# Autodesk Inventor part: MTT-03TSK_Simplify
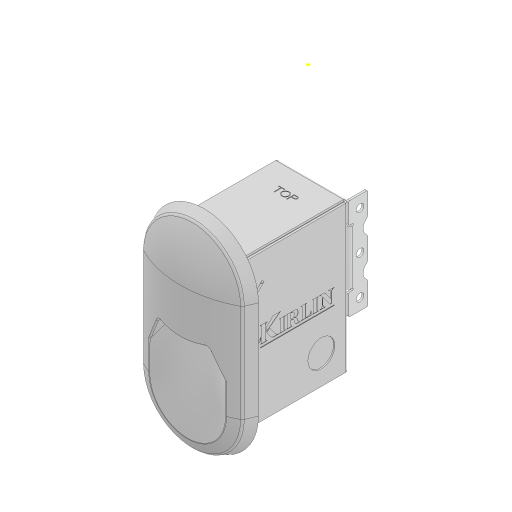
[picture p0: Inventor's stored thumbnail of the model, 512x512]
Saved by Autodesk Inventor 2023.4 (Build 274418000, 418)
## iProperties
Created: 2024-02
Part Number: MTT-03TSK_Simplify
Material: Generic
Document SubType Name: Modeling
Designer: sjaafar
Mass: 133.424 g
Surface Area: 1388.59 cm^2
Volume: 133.424 cm^3
Density: 1 g/cm^3
Appearance: Default
description: 0:0:Hitsville Task Light
manufacturer: 0:0:The Kirlin Company
model: 0:0:MTT-03TSK
url: 0:0:
load_classification: Lighting
motor: 0 ul
Author: sjaafar
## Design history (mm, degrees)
derived "MTT-03TSKR.iam"
  node "902001-00-00.iam:1::902000-00-00.iam:1"
body "Solid1"
node "904003-XX-XX.iam:1::503002-00-00.ipt:1"
node "904003-XX-XX.iam:1::503002-00-00.ipt:2"
node "904003-XX-XX.iam:1::510200-00-00.ipt:1"
node "904003-XX-XX.iam:1::502308-00-00.ipt:1"
node "904003-XX-XX.iam:1::502308-00-00.ipt:2"
node "904003-XX-XX.iam:1::725801-00-00.ipt:1"
node "904003-XX-XX.iam:1::904000-XX-XX.iam:1::810001.ipt:1"
sketch "Sketch17"
  geometry: 1 further point
node "904003-XX-XX.iam:1::904000-XX-XX.iam:1::502307-00-00.ipt:4"
node "904003-XX-XX.iam:1::904000-XX-XX.iam:1::502307-00-00.ipt:5"
node "904003-XX-XX.iam:1::904000-XX-XX.iam:1::502307-00-00.ipt:6"
node "904003-XX-XX.iam:1::904000-XX-XX.iam:1::741000.ipt:1"
sketch "Sketch40"
  geometry: 1 further point
sketch "Sketch 2"
  geometry: C1 r 0.508 at (0, 0) reference; C2 r 1.143 at (0, 0) reference
node "902001-00-00.iam:1::902000-00-00.iam:1::810002.ipt:1"
sketch "Sketch71"
  geometry: 2 further points
node "902001-00-00.iam:1::902000-00-00.iam:1::810000.ipt:1"
node "902001-00-00.iam:1::902000-00-00.iam:1::810004.ipt:1"
node "902001-00-00.iam:1::902000-00-00.iam:1::M4 Rivet.ipt:1"
node "902001-00-00.iam:1::902000-00-00.iam:1::670033-00-00.iam:2::"
node "1"
node "902001-00-00.iam:1::509447-00-00.ipt:1"
node "902001-00-00.iam:1::502040-00-00.ipt:1"
node "902001-00-00.iam:1::502040-00-00.ipt:2"
